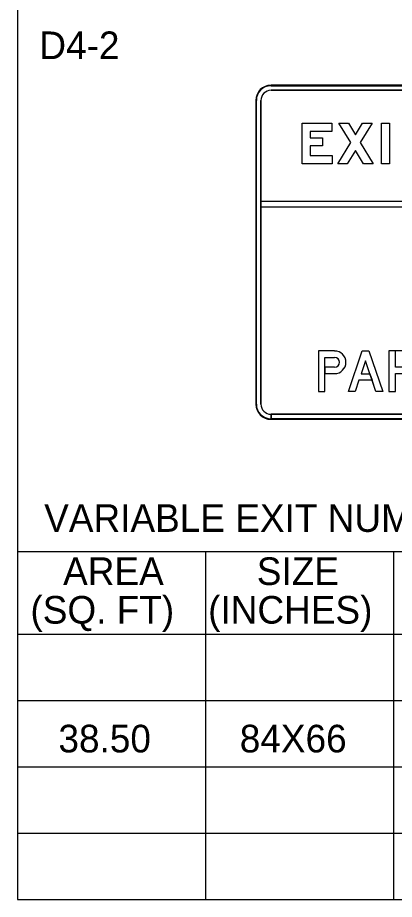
# Model space of a CAD drawing. Extents: x 0 to 2011, y -71 to 1183.
# Drawn here: x 319.3 to 362.9, y 393.2 to 495.3 of the extents above; entities that cross this region are included whole.
import ezdxf

# ---------------------------------------------------------------- set-up
doc = ezdxf.new("R2010")
doc.units = 0
for name, color, linetype in [('GSBWFILL', 7, 'Continuous'), ('Level 2', 7, 'Continuous'), ('Level 5', 7, 'Continuous')]:
    doc.layers.add(name, color=color, linetype=linetype)

msp = doc.modelspace()

# ---------------------------------------------------------------- linework, layer by layer
at = {"layer": 'GSBWFILL'}
for p, q in [((394.33, 487.44), (348.63, 487.44)), ((394.33, 487.44), (348.63, 487.44)), ((394.33, 487.44), (348.63, 487.44)), ((394.33, 487.44), (348.63, 487.44)), ((348.63, 487.38), (394.33, 487.38)), ((394.33, 486.85), (348.63, 486.85)), ((348.63, 486.85), (394.33, 486.85)), ((348.63, 486.85), (394.33, 486.85)), ((346.87, 485.68), (346.87, 450.52)), ((346.87, 485.68), (346.87, 450.52)), ((346.87, 485.68), (346.87, 450.52)), ((346.87, 485.68), (346.87, 450.52)), ((346.93, 450.52), (346.93, 485.68)), ((347.45, 485.68), (347.45, 450.52)), ((347.45, 450.52), (347.45, 485.68)), ((347.45, 450.52), (347.45, 485.68)), ((395.5, 473.96), (347.45, 473.96)), ((347.45, 473.96), (347.45, 473.37)), ((395.5, 473.96), (347.45, 473.96)), ((347.45, 473.96), (347.45, 473.37)), ((395.5, 473.96), (347.45, 473.96)), ((347.45, 473.96), (347.45, 473.37)), ((347.45, 473.37), (395.5, 473.37)), ((347.45, 473.37), (395.5, 473.37)), ((347.45, 473.37), (395.5, 473.37)), ((354.86, 455.93), (355.99, 455.93)), ((354.86, 455.93), (355.99, 455.93)), ((354.86, 454.05), (355.99, 454.05)), ((348.63, 449.35), (394.33, 449.35)), ((348.63, 448.77), (348.63, 449.35)), ((394.33, 449.35), (348.63, 449.35)), ((348.63, 449.35), (348.63, 448.77)), ((348.63, 448.77), (348.63, 449.35)), ((394.33, 449.35), (348.63, 449.35)), ((348.63, 449.35), (348.63, 448.77)), ((348.63, 448.77), (348.63, 448.82)), ((394.33, 448.82), (348.63, 448.82)), ((348.63, 448.82), (348.63, 448.77)), ((348.63, 448.77), (394.33, 448.77)), ((348.63, 448.77), (394.33, 448.77)), ((348.63, 448.77), (394.33, 448.77)), ((348.63, 448.77), (394.33, 448.77))]:
    msp.add_line(p, q, dxfattribs=at)
for points in [[(355.66, 483.04), (355.66, 482.1), (353.17, 482.1), (353.17, 481.35), (354.58, 481.35), (354.58, 480.42), (353.17, 480.42), (353.17, 479.29), (355.7, 479.29), (355.7, 478.35), (352.24, 478.35), (352.24, 483.04)], [(355.66, 483.04), (355.66, 482.1), (353.17, 482.1), (353.17, 481.35), (354.58, 481.35), (354.58, 480.42), (353.17, 480.42), (353.17, 479.29), (355.7, 479.29), (355.7, 478.35), (352.24, 478.35), (352.24, 483.04)], [(355.66, 483.04), (355.66, 482.1), (353.17, 482.1), (353.17, 481.35), (354.58, 481.35), (354.58, 480.42), (353.17, 480.42), (353.17, 479.29), (355.7, 479.29), (355.7, 478.35), (352.24, 478.35), (352.24, 483.04)], [(359.34, 478.35), (358.4, 479.9), (357.46, 478.35), (356.36, 478.35), (357.85, 480.79), (356.48, 483.04), (357.58, 483.04), (358.4, 481.69), (359.22, 483.04), (360.32, 483.04), (358.95, 480.79), (360.44, 478.35)], [(359.34, 478.35), (358.4, 479.9), (357.46, 478.35), (356.36, 478.35), (357.85, 480.79), (356.48, 483.04), (357.58, 483.04), (358.4, 481.69), (359.22, 483.04), (360.32, 483.04), (358.95, 480.79), (360.44, 478.35)], [(359.34, 478.35), (358.4, 479.9), (357.46, 478.35), (356.36, 478.35), (357.85, 480.79), (356.48, 483.04), (357.58, 483.04), (358.4, 481.69), (359.22, 483.04), (360.32, 483.04), (358.95, 480.79), (360.44, 478.35)], [(361.42, 483.04), (362.36, 483.04), (362.36, 478.35), (361.42, 478.35)], [(361.42, 483.04), (362.36, 483.04), (362.36, 478.35), (361.42, 478.35)], [(361.42, 483.04), (362.36, 483.04), (362.36, 478.35), (361.42, 478.35)], [(358.81, 453.28), (358.37, 451.99), (357.58, 451.99), (359.17, 456.68), (359.97, 456.68), (361.56, 451.99), (360.77, 451.99), (360.33, 453.28)], [(357.58, 451.99), (359.17, 456.68), (359.97, 456.68), (361.56, 451.99), (360.77, 451.99), (359.57, 455.52), (359.06, 454.03), (360.08, 454.03), (360.33, 453.28), (358.81, 453.28), (358.37, 451.99)], [(357.58, 451.99), (359.17, 456.68), (359.97, 456.68), (361.56, 451.99), (360.77, 451.99), (359.57, 455.52), (359.06, 454.03), (360.08, 454.03), (360.33, 453.28), (358.81, 453.28), (358.37, 451.99)], [(359.06, 454.03), (360.08, 454.03), (359.57, 455.52)]]:
    msp.add_lwpolyline(points, close=True, dxfattribs=at)
for points in [[(355.99, 456.68), (354.11, 456.68), (354.11, 451.99), (354.86, 451.99), (354.86, 454.05)], [(355.99, 456.68), (354.11, 456.68), (354.11, 451.99), (354.86, 451.99), (354.86, 455.93)], [(355.99, 456.68), (354.11, 456.68), (354.11, 451.99), (354.86, 451.99), (354.86, 455.93)], [(364.05, 454.8), (363.02, 454.8), (363.02, 456.68), (362.27, 456.68), (362.27, 451.99), (363.02, 451.99), (363.02, 454.05), (363.9, 454.05), (364.65, 451.99), (365.45, 451.99), (364.64, 454.19)], [(364.05, 454.8), (363.02, 454.8), (363.02, 456.68), (362.27, 456.68), (362.27, 451.99), (363.02, 451.99), (363.02, 454.05), (363.9, 454.05), (364.65, 451.99), (365.45, 451.99), (364.64, 454.19)], [(364.05, 456.68), (362.27, 456.68), (362.27, 451.99), (363.02, 451.99), (363.02, 454.05), (363.9, 454.05), (364.65, 451.99), (365.45, 451.99), (364.64, 454.19)], [(355.99, 454.8), (354.86, 454.8), (354.86, 455.93), (355.99, 455.93)], [(355.99, 454.8), (354.86, 454.8), (354.86, 454.05), (355.99, 454.05)], [(355.99, 454.8), (354.86, 454.8), (354.86, 454.05), (355.99, 454.05)]]:
    msp.add_lwpolyline(points, dxfattribs=at)
for centre, radius, start, end in [((348.63, 485.68), 1.76, 90, 180), ((348.63, 485.68), 1.76, 90, 180), ((348.63, 485.68), 1.76, 90, 180), ((348.63, 485.68), 1.76, 90, 180), ((348.63, 485.68), 1.7, 90, 180), ((348.63, 485.68), 1.17, 90, 180), ((348.63, 485.68), 1.17, 90, 180), ((348.63, 485.68), 1.17, 90, 180), ((355.99, 455.36), 1.31, 270, 90), ((355.99, 455.36), 1.31, 270, 90), ((355.99, 455.36), 1.31, 270, 90), ((355.99, 455.36), 0.562, 270, 90), ((355.99, 455.36), 0.562, 270, 90), ((355.99, 455.36), 0.562, 270, 90), ((348.63, 450.52), 1.76, 180, 270), ((348.63, 450.52), 1.76, 180, 270), ((348.63, 450.52), 1.76, 180, 270), ((348.63, 450.52), 1.76, 180, 270), ((348.63, 450.52), 1.7, 180, 270), ((348.63, 450.52), 1.17, 180, 270), ((348.63, 450.52), 1.17, 180, 270), ((348.63, 450.52), 1.17, 180, 270)]:
    msp.add_arc(centre, radius, start, end, dxfattribs=at)
at = {"layer": 'Level 2'}
for p, q in [((319.3, 433.47), (424.05, 433.47)), ((341.05, 433.47), (341.05, 393.19)), ((362.8, 433.47), (362.8, 393.19)), ((319.3, 423.88), (424.05, 423.88)), ((319.3, 416.2), (424.05, 416.2)), ((319.3, 408.53), (424.05, 408.53)), ((319.3, 400.86), (424.05, 400.86))]:
    msp.add_line(p, q, dxfattribs=at)
msp.add_lwpolyline([(424.05, 496.81), (319.3, 496.81), (319.3, 393.19), (424.05, 393.19)], close=True, dxfattribs=at)

# ---------------------------------------------------------------- texts
for s, p in [('D4-2', (321.81, 490.46)), ('VARIABLE EXIT NUMBER', (322.37, 435.73)), ('SIZE', (346.98, 429.58)), ('AREA', (324.56, 429.58)), ('(SQ. FT)', (320.78, 425.11)), ('(INCHES)', (341.35, 425.11))]:
    msp.add_text(s, height=3.2, dxfattribs=at).set_placement(p)
at = {"layer": 'Level 5'}
for s, p in [('38.50', (324.02, 410.2)), ('84X66', (345.01, 410.2))]:
    msp.add_text(s, height=3.2, dxfattribs=at).set_placement(p)

doc.saveas('drawing.dxf')
